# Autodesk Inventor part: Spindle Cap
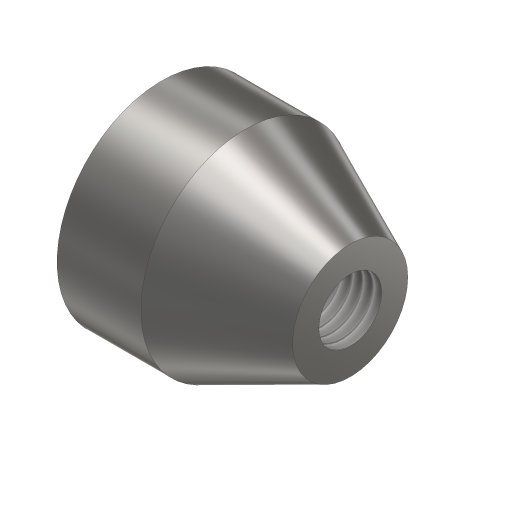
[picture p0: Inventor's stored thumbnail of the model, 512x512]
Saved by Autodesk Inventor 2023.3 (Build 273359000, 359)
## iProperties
Created: 2020-10
Part Number: Spindle Cap
Material: Steel, Mild
Document SubType Name: Modeling
Designer: User
Density: 7.85 g/cm^3
Appearance: Semi-Polished
Mass: 17.2754 g
Surface Area: 13.8299 cm^2
Volume: 2.20069 cm^3
Author: User
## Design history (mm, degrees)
sketch "Sketch1"
  geometry: L1 (0, 0)-(0, 10); L2 (0, 10)-(8, 10); L3 (8, 10)-(18, 5.5); L4 (18, 5.5)-(18, 0); L5 (18, 0)-(0, 0); L6 (0, 7)-(6, 7); L7 (6, 7)-(6, 3); L8 (6, 3)-(18, 3)
  constraints: 16 end point, 4 perpendicular, 2 point on line, 1 horizontal, 1 parallel, 1 vertical
  dimensions: "d0" = 10 distance of L1.start L1.end; "d2" = 18 distance of L4.end L1.start; "d3" = 5.5 distance of L3.end L4.end; "d4" = 3 distance between parallel lines of L5 L8; "d5" = 7 distance between parallel lines of L5 L6; "d6" = 6 distance between parallel lines of L1 L7; "d7" = 10 distance from line of L4 L2.end
revolve "Revolution1" sketch "Sketch1" stored, may be unused: angle "d8" = 90 deg
thread "Thread1" dims "d9" = 12, "d10" = 0
body "Solid1"
